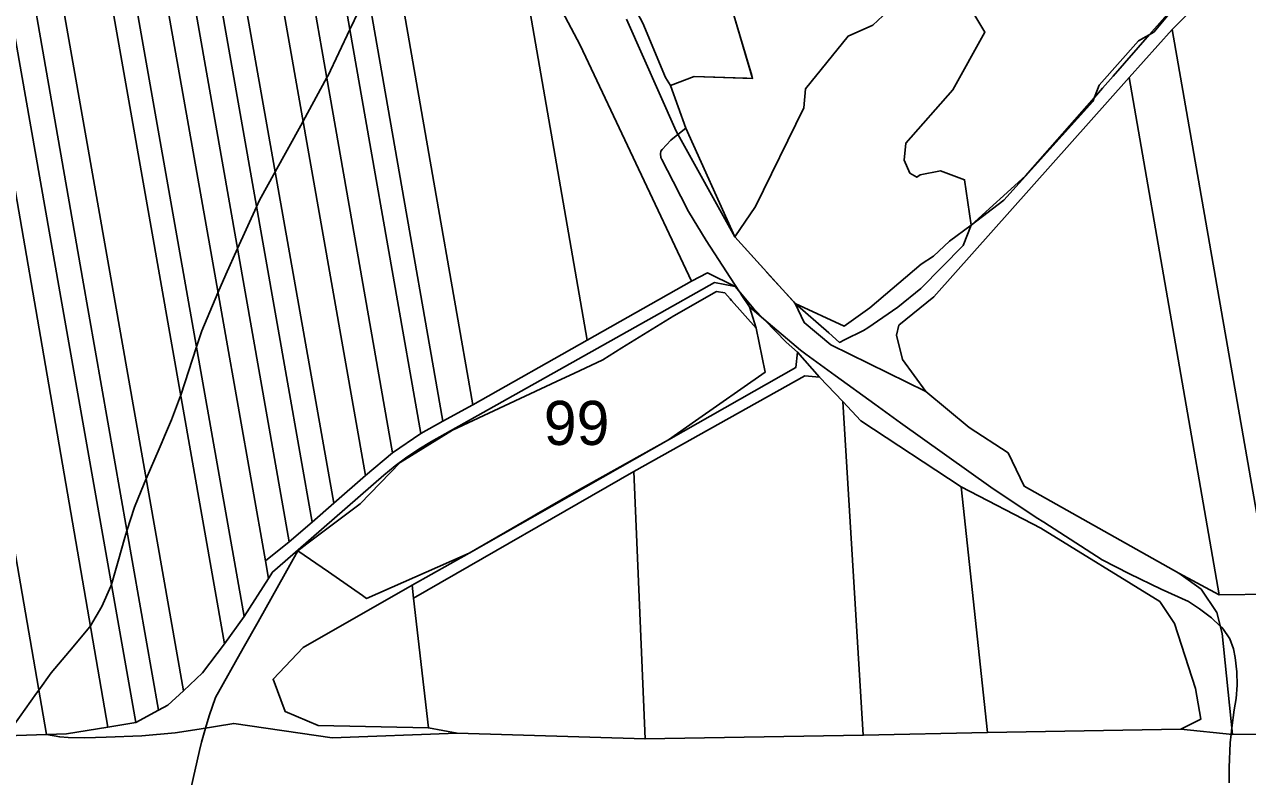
# Model space of a CAD drawing. Extents: x -521939 to -516426, y -1197857 to -1189551.
# Drawn here: x -518926.4 to -518510, y -1193004.4 to -1192748.4 of the extents above; entities that cross this region are included whole.
import ezdxf

# ---------------------------------------------------------------- set-up
doc = ezdxf.new("R2010")
doc.units = 0
for name, color, linetype in [('95560013', 7, 'Continuous'), ('95600013', 7, 'Continuous'), ('95610013', 7, 'Continuous'), ('95620013', 7, 'Continuous'), ('95640013', 7, 'Continuous'), ('95660013', 7, 'Continuous')]:
    doc.layers.add(name, color=color, linetype=linetype)

msp = doc.modelspace()

# ---------------------------------------------------------------- linework, layer by layer
at = {"layer": '95560013'}
for points in [[(-518883.96, -1192813.68), (-518944.06, -1192473.16), (-518936.14, -1192471.19), (-518905.14, -1192646.71), (-518874.14, -1192822.23), (-518851.6, -1192949.85), (-518858.28, -1192959.18)], [(-518924.38, -1192478.48), (-518893.68, -1192652.1), (-518862.98, -1192825.72), (-518844.38, -1192930.91), (-518843.32, -1192936.91), (-518851.6, -1192949.85), (-518874.14, -1192822.23), (-518905.14, -1192646.71), (-518936.14, -1192471.19), (-518930.23, -1192469.72)], [(-518960.05, -1192477.14), (-518952.49, -1192475.3), (-518944.06, -1192473.16), (-518883.96, -1192813.68), (-518858.28, -1192959.18), (-518865.75, -1192969.09), (-518872.22, -1192975.24), (-518898.04, -1192828.81)], [(-518969.05, -1192479.46), (-518937.77, -1192657.48), (-518906.62, -1192834.76), (-518880.78, -1192981.82), (-518888.53, -1192985.94), (-518914.36, -1192839.45), (-518945.91, -1192660.52), (-518977.46, -1192481.59)], [(-518872.22, -1192975.24), (-518877.56, -1192980.06), (-518880.78, -1192981.82), (-518906.62, -1192834.76), (-518937.77, -1192657.48), (-518969.05, -1192479.46), (-518960.05, -1192477.14), (-518898.04, -1192828.81)], [(-518911.42, -1192497.6), (-518879.74, -1192677.45), (-518848.71, -1192853.61), (-518836.23, -1192924.46), (-518844.38, -1192930.91), (-518862.98, -1192825.72), (-518893.68, -1192652.1), (-518924.38, -1192478.48)], [(-518897.98, -1192987.5), (-518912.11, -1192989.78), (-518918.87, -1192990), (-518944.92, -1192840.14), (-518975.46, -1192664.45), (-519006, -1192488.76), (-518985.24, -1192483.53), (-518954.55, -1192660.79), (-518920.43, -1192857.84)], [(-518945.91, -1192660.52), (-518914.36, -1192839.45), (-518888.53, -1192985.94), (-518897.98, -1192987.5), (-518920.43, -1192857.84), (-518954.55, -1192660.79), (-518985.24, -1192483.53), (-518977.46, -1192481.59)], [(-518932.53, -1192990.45), (-518956.69, -1192853.01), (-518988.4, -1192672.62), (-519020.11, -1192492.23), (-519006, -1192488.76), (-518975.46, -1192664.45), (-518944.92, -1192840.14), (-518918.87, -1192990)], [(-518911.42, -1192497.6), (-518899.32, -1192515.59), (-518868.08, -1192692.89), (-518836.84, -1192870.19), (-518828.46, -1192917.75), (-518836.23, -1192924.46), (-518848.71, -1192853.61), (-518879.74, -1192677.45)], [(-518888.04, -1192532.35), (-518856.66, -1192710.07), (-518825.31, -1192887.62), (-518821.12, -1192911.35), (-518828.46, -1192917.75), (-518836.84, -1192870.19), (-518868.08, -1192692.89), (-518899.32, -1192515.59)], [(-518888.04, -1192532.35), (-518871, -1192557.6), (-518840.17, -1192732.41), (-518810.28, -1192901.89), (-518821.12, -1192911.35), (-518825.31, -1192887.62), (-518856.66, -1192710.07)], [(-518871, -1192557.6), (-518856.13, -1192579.88), (-518825.13, -1192756.87), (-518801.08, -1192894.18), (-518810.28, -1192901.89), (-518840.17, -1192732.41)], [(-518810.26, -1192780.53), (-518791.49, -1192887.61), (-518801.08, -1192894.18), (-518825.13, -1192756.87), (-518856.13, -1192579.88), (-518842.04, -1192599.23)], [(-518842.04, -1192599.23), (-518831.07, -1192614.22), (-518800.38, -1192789.53), (-518783.94, -1192883.44), (-518791.49, -1192887.61), (-518810.26, -1192780.53)], [(-518786.19, -1192806.65), (-518773.74, -1192877.8), (-518783.94, -1192883.44), (-518800.38, -1192789.53), (-518831.07, -1192614.22), (-518816.35, -1192634.29)], [(-518759.71, -1192712.86), (-518734.84, -1192855.82), (-518773.74, -1192877.8), (-518786.19, -1192806.65), (-518816.35, -1192634.29)], [(-518699.31, -1192835.73), (-518734.84, -1192855.82), (-518759.71, -1192712.86), (-518737.24, -1192755.42)]]:
    msp.add_lwpolyline(points, close=True, dxfattribs=at)
at = {"layer": '95600013'}
msp.add_lwpolyline([(-518678.47, -1192766.77), (-518698.41, -1192766.11), (-518706.48, -1192769.16), (-518708.17, -1192766.43), (-518715.91, -1192747.94), (-518717.63, -1192744.59), (-518698.25, -1192731.89), (-518697.23, -1192734.65), (-518695.01, -1192738.2), (-518684.92, -1192745.27)], close=True, dxfattribs=at)
at = {"layer": '95610013'}
for points in [[(-518508.45, -1192727.51), (-518477.72, -1192903.66), (-518469.02, -1192953.53), (-518485.76, -1192945.93), (-518494.49, -1192943.25), (-518502, -1192942.29), (-518535.64, -1192750.15), (-518525.8, -1192740.06), (-518518.9, -1192734.37)], [(-518502, -1192942.29), (-518519.63, -1192942.55), (-518550.24, -1192766.43), (-518535.64, -1192750.15)], [(-518629.44, -1192854.17), (-518628.75, -1192850.78), (-518616.82, -1192841.07), (-518550.24, -1192766.43), (-518519.63, -1192942.55), (-518533.4, -1192935.15), (-518586.01, -1192905.56), (-518591.47, -1192894.23), (-518604.74, -1192885.62), (-518619.45, -1192873.36), (-518627.5, -1192862.37)], [(-518718.9, -1192900.54), (-518660.71, -1192868.02), (-518655.74, -1192868.43), (-518647.77, -1192876.73), (-518640.83, -1192990.3), (-518715.07, -1192991.54)], [(-518640.83, -1192990.3), (-518647.77, -1192876.73), (-518641.65, -1192883.29), (-518607.43, -1192905.72), (-518598.55, -1192989.35)], [(-518793.93, -1192943.67), (-518718.9, -1192900.54), (-518715.07, -1192991.54), (-518779.05, -1192989.61), (-518788.86, -1192987.81)], [(-518525.88, -1192984.87), (-518532.67, -1192988.21), (-518598.55, -1192989.35), (-518607.43, -1192905.72), (-518580.39, -1192919.85), (-518539.85, -1192944.8), (-518534.83, -1192952.24), (-518527.68, -1192974.39)], [(-518441.46, -1192991.31), (-518473.62, -1192989.89), (-518515.05, -1192990), (-518518.64, -1192955.67), (-518520.44, -1192948.52), (-518525.77, -1192940.63), (-518533.4, -1192935.15), (-518519.63, -1192942.55), (-518502, -1192942.29), (-518494.49, -1192943.25), (-518485.76, -1192945.93), (-518469.02, -1192953.53), (-518442.41, -1192965.03), (-518428.88, -1192969.95), (-518413.6, -1192975.54), (-518404.12, -1192979.78), (-518382.7, -1192989.47), (-518370.63, -1193001.75), (-518365.62, -1193004.33), (-518354.48, -1193010.65), (-518375.31, -1193003.18), (-518388.43, -1193000.81), (-518414.09, -1192994.92)], [(-518793.93, -1192943.67), (-518788.86, -1192987.81), (-518826.37, -1192986.96), (-518837.66, -1192982.24), (-518841.74, -1192971.22), (-518831.52, -1192960.42), (-518794.45, -1192939.2)]]:
    msp.add_lwpolyline(points, close=True, dxfattribs=at)
at = {"layer": '95620013'}
for points in [[(-518630.7, -1192742.29), (-518637.58, -1192748.61), (-518645.97, -1192752.33), (-518660.51, -1192770.33), (-518660.99, -1192776.79), (-518677.53, -1192810.38), (-518684.56, -1192820.7), (-518704.53, -1192784.74), (-518721.46, -1192746.65)], [(-518535.48, -1192743.39), (-518541.9, -1192751.07), (-518547.09, -1192753.93), (-518560.44, -1192769.05), (-518562.68, -1192774.61), (-518592.99, -1192808.25), (-518604.02, -1192816.75), (-518606.32, -1192801.23), (-518614.52, -1192798.26), (-518621.42, -1192799.62), (-518622.62, -1192800.39), (-518624.93, -1192798.97), (-518626.89, -1192794.58), (-518626.29, -1192788.78), (-518610.31, -1192770.59), (-518599.39, -1192750.98), (-518602.87, -1192745.31)], [(-518715.91, -1192747.94), (-518708.17, -1192766.43), (-518706.48, -1192769.16), (-518698.41, -1192766.11), (-518678.47, -1192766.77), (-518684.92, -1192745.27)]]:
    msp.add_lwpolyline(points, dxfattribs=at)
msp.add_lwpolyline([(-518821.67, -1192991.23), (-518855.17, -1192986.26), (-518866.91, -1192988.22), (-518875.1, -1192989.54), (-518886.48, -1192990.45), (-518898.64, -1192990.98), (-518905.82, -1192991.22), (-518911.52, -1192991.08), (-518914.36, -1192990.89), (-518918.87, -1192990), (-518912.11, -1192989.78), (-518897.98, -1192987.5), (-518888.53, -1192985.94), (-518880.78, -1192981.82), (-518877.56, -1192980.06), (-518872.22, -1192975.24), (-518865.75, -1192969.09), (-518858.28, -1192959.18), (-518851.6, -1192949.85), (-518843.32, -1192936.91), (-518841.93, -1192934.75), (-518837.69, -1192931.06), (-518804.08, -1192901.83), (-518800.23, -1192898.65), (-518796.23, -1192895.68), (-518792.08, -1192892.91), (-518787.8, -1192890.35), (-518712.04, -1192847.75), (-518691.51, -1192836.21), (-518684.41, -1192837.53), (-518678.07, -1192845.16), (-518667.06, -1192856.49), (-518663.19, -1192859.9), (-518663.78, -1192865.16), (-518707.15, -1192889.79), (-518774.96, -1192928.3), (-518794.45, -1192939.2), (-518831.52, -1192960.42), (-518841.74, -1192971.22), (-518837.66, -1192982.24), (-518826.37, -1192986.96), (-518788.86, -1192987.81), (-518779.05, -1192989.61)], close=True, dxfattribs=at)
at = {"layer": '95640013'}
for points in [[(-518721.46, -1192746.65), (-518704.53, -1192784.74), (-518684.56, -1192820.7), (-518663.98, -1192843.4), (-518660.97, -1192849.86), (-518651.89, -1192857.45), (-518619.45, -1192873.36), (-518604.74, -1192885.62), (-518591.47, -1192894.23), (-518586.01, -1192905.56), (-518533.4, -1192935.15), (-518525.77, -1192940.63), (-518520.44, -1192948.52), (-518518.64, -1192955.67), (-518515.05, -1192990), (-518532.67, -1192988.21), (-518525.88, -1192984.87), (-518527.68, -1192974.39), (-518534.83, -1192952.24), (-518539.85, -1192944.8), (-518580.39, -1192919.85), (-518607.43, -1192905.72), (-518641.65, -1192883.29), (-518647.77, -1192876.73), (-518655.74, -1192868.43), (-518663.19, -1192859.9), (-518667.06, -1192856.49), (-518678.07, -1192845.16), (-518684.41, -1192837.53), (-518693.82, -1192832.93), (-518699.31, -1192835.73), (-518737.24, -1192755.42), (-518759.71, -1192712.86)], [(-518602.87, -1192745.31), (-518599.39, -1192750.98), (-518610.31, -1192770.59), (-518626.29, -1192788.78), (-518626.89, -1192794.58), (-518624.93, -1192798.97), (-518622.62, -1192800.39), (-518621.42, -1192799.62), (-518614.52, -1192798.26), (-518606.32, -1192801.23), (-518604.02, -1192816.75), (-518611.45, -1192822.14), (-518616.94, -1192827.29), (-518621.09, -1192829.97), (-518638.52, -1192844.83), (-518647.3, -1192851.1), (-518663.98, -1192843.4), (-518684.56, -1192820.7), (-518677.53, -1192810.38), (-518660.99, -1192776.79), (-518660.51, -1192770.33), (-518645.97, -1192752.33), (-518637.58, -1192748.61), (-518630.7, -1192742.29)], [(-518525.8, -1192740.06), (-518535.64, -1192750.15), (-518550.24, -1192766.43), (-518616.82, -1192841.07), (-518628.75, -1192850.78), (-518629.44, -1192854.17), (-518627.5, -1192862.37), (-518619.45, -1192873.36), (-518651.89, -1192857.45), (-518660.97, -1192849.86), (-518663.98, -1192843.4), (-518647.3, -1192851.1), (-518638.52, -1192844.83), (-518621.09, -1192829.97), (-518616.94, -1192827.29), (-518611.45, -1192822.14), (-518604.02, -1192816.75), (-518592.99, -1192808.25), (-518562.68, -1192774.61), (-518560.44, -1192769.05), (-518547.09, -1192753.93), (-518541.9, -1192751.07), (-518535.48, -1192743.39)], [(-518932.53, -1192990.45), (-518918.87, -1192990), (-518914.36, -1192990.89), (-518911.52, -1192991.08), (-518905.82, -1192991.22), (-518898.64, -1192990.98), (-518886.48, -1192990.45), (-518875.1, -1192989.54), (-518866.91, -1192988.22), (-518855.17, -1192986.26), (-518821.67, -1192991.23), (-518779.05, -1192989.61), (-518715.07, -1192991.54), (-518640.83, -1192990.3), (-518598.55, -1192989.35), (-518532.67, -1192988.21), (-518515.05, -1192990), (-518473.62, -1192989.89)]]:
    msp.add_lwpolyline(points, dxfattribs=at)
for points in [[(-518734.84, -1192855.82), (-518699.31, -1192835.73), (-518693.82, -1192832.93), (-518684.41, -1192837.53), (-518691.51, -1192836.21), (-518712.04, -1192847.75), (-518787.8, -1192890.35), (-518792.08, -1192892.91), (-518796.23, -1192895.68), (-518800.23, -1192898.65), (-518804.08, -1192901.83), (-518837.69, -1192931.06), (-518841.93, -1192934.75), (-518843.32, -1192936.91), (-518844.38, -1192930.91), (-518836.23, -1192924.46), (-518828.46, -1192917.75), (-518821.12, -1192911.35), (-518810.28, -1192901.89), (-518801.08, -1192894.18), (-518791.49, -1192887.61), (-518783.94, -1192883.44), (-518773.74, -1192877.8)], [(-518655.74, -1192868.43), (-518660.71, -1192868.02), (-518718.9, -1192900.54), (-518793.93, -1192943.67), (-518794.45, -1192939.2), (-518774.96, -1192928.3), (-518707.15, -1192889.79), (-518663.78, -1192865.16), (-518663.19, -1192859.9)]]:
    msp.add_lwpolyline(points, close=True, dxfattribs=at)
at = {"layer": '95660013'}
for points in [[(-518930.03, -1192986.91), (-518922.26, -1192976.01), (-518921.49, -1192974.93), (-518917.28, -1192969.06), (-518911.02, -1192961.64), (-518904.18, -1192953.41), (-518903.95, -1192953.03), (-518900.01, -1192946.46), (-518897, -1192939.62), (-518896.81, -1192938.98), (-518894.45, -1192931.04), (-518892.24, -1192923.04), (-518891.5, -1192920.78), (-518888.88, -1192912.72), (-518885.64, -1192904.61), (-518884.95, -1192903.02), (-518880.54, -1192892.79), (-518879.56, -1192890.48), (-518878.73, -1192888.53), (-518876.36, -1192882.94), (-518873.58, -1192875.75), (-518873.21, -1192874.61), (-518867.81, -1192858.07), (-518866.05, -1192852.68), (-518860.51, -1192839.72), (-518857.82, -1192833.44), (-518853.82, -1192824.62), (-518847.37, -1192810.43), (-518846.34, -1192808.17), (-518841.03, -1192798.57), (-518832.32, -1192782.79), (-518831.54, -1192781.36), (-518823.44, -1192766.5), (-518823.16, -1192765.98), (-518815.6, -1192750.07), (-518809.53, -1192737.29)], [(-518809.53, -1192737.29), (-518815.6, -1192750.07), (-518823.16, -1192765.98), (-518823.44, -1192766.5), (-518831.54, -1192781.36), (-518832.32, -1192782.79), (-518841.03, -1192798.57), (-518846.34, -1192808.17), (-518847.37, -1192810.43), (-518853.82, -1192824.62), (-518857.82, -1192833.44), (-518860.51, -1192839.72), (-518866.05, -1192852.68), (-518867.81, -1192858.07), (-518873.21, -1192874.61), (-518873.58, -1192875.75), (-518876.36, -1192882.94), (-518878.73, -1192888.53), (-518879.56, -1192890.48), (-518880.54, -1192892.79), (-518884.95, -1192903.02), (-518885.64, -1192904.61), (-518888.88, -1192912.72), (-518891.5, -1192920.78), (-518892.24, -1192923.04), (-518894.45, -1192931.04), (-518896.81, -1192938.98), (-518897, -1192939.62), (-518900.01, -1192946.46), (-518903.95, -1192953.03), (-518904.18, -1192953.41), (-518911.02, -1192961.64), (-518917.28, -1192969.06), (-518921.49, -1192974.93), (-518922.26, -1192976.01), (-518930.03, -1192986.91)], [(-518516.26, -1193006.51), (-518516.26, -1193003.71), (-518516.18, -1193001.24), (-518515.91, -1192992.86), (-518515.55, -1192989.95), (-518515.28, -1192987.79), (-518514.51, -1192981.61), (-518513.81, -1192977.81), (-518513.46, -1192973.21), (-518513.58, -1192968.72), (-518514.16, -1192963.82), (-518514.74, -1192960.9), (-518516.02, -1192957.52), (-518518.36, -1192954.02), (-518519.28, -1192953.13), (-518522.21, -1192950.29), (-518526.29, -1192947.31), (-518530.02, -1192944.75), (-518539.35, -1192940.55), (-518550.14, -1192935.36), (-518559.41, -1192930.63), (-518579.36, -1192917.82), (-518581.93, -1192916.17), (-518597.38, -1192905.91), (-518628.12, -1192883.98), (-518636.83, -1192877.66), (-518650.39, -1192867.82), (-518660.35, -1192860.61), (-518662.17, -1192859.29), (-518674.68, -1192848.64), (-518679.55, -1192844.5), (-518682.12, -1192840.63), (-518682.62, -1192839.86), (-518683.15, -1192839.05), (-518694.31, -1192821.9), (-518700.26, -1192812.1), (-518705.51, -1192801.83), (-518709.36, -1192794.37), (-518709.68, -1192793.7), (-518709.88, -1192792.44), (-518709.71, -1192791.57), (-518709.33, -1192790.9), (-518706.32, -1192787.78), (-518703.91, -1192785.85), (-518701.16, -1192783.64), (-518684.56, -1192820.7), (-518673.64, -1192832.74), (-518673.59, -1192832.79), (-518664.5, -1192842.82), (-518663.98, -1192843.4), (-518652.55, -1192853.38), (-518648.85, -1192856.61), (-518647.17, -1192855.77), (-518640.72, -1192852.56), (-518639.28, -1192851.59), (-518629.03, -1192844.66), (-518621.2, -1192838.31), (-518606.75, -1192823.64), (-518604.02, -1192816.75), (-518585.53, -1192799.87), (-518562.11, -1192773.2), (-518559.38, -1192770.09), (-518555.73, -1192765.95), (-518543.3, -1192751.84), (-518534.68, -1192742.05)], [(-518534.68, -1192742.05), (-518543.3, -1192751.84), (-518555.73, -1192765.95), (-518559.38, -1192770.09), (-518562.11, -1192773.2), (-518585.53, -1192799.87), (-518604.02, -1192816.75), (-518606.75, -1192823.64), (-518621.2, -1192838.31), (-518629.03, -1192844.66), (-518639.28, -1192851.59), (-518640.72, -1192852.56), (-518647.17, -1192855.77), (-518648.85, -1192856.61), (-518652.55, -1192853.38), (-518663.98, -1192843.4), (-518664.5, -1192842.82), (-518673.59, -1192832.79), (-518673.64, -1192832.74), (-518684.56, -1192820.7), (-518701.16, -1192783.64), (-518706.48, -1192769.16), (-518698.41, -1192766.11), (-518680.89, -1192766.69), (-518680.5, -1192766.7), (-518678.47, -1192766.77), (-518678.76, -1192765.79), (-518684.92, -1192745.27)], [(-518684.92, -1192745.27), (-518678.76, -1192765.79), (-518678.47, -1192766.77), (-518680.5, -1192766.7), (-518680.89, -1192766.69), (-518698.41, -1192766.11), (-518706.48, -1192769.16), (-518701.16, -1192783.64), (-518703.91, -1192785.85), (-518706.32, -1192787.78), (-518709.33, -1192790.9), (-518709.71, -1192791.57), (-518709.88, -1192792.44), (-518709.68, -1192793.7), (-518709.36, -1192794.37), (-518705.51, -1192801.83), (-518700.26, -1192812.1), (-518694.31, -1192821.9), (-518683.15, -1192839.05), (-518682.62, -1192839.86), (-518682.12, -1192840.63), (-518679.55, -1192844.5), (-518677.32, -1192851.77), (-518685.71, -1192842.31), (-518686.16, -1192841.8), (-518687.95, -1192839.78), (-518690.83, -1192839.31), (-518705.27, -1192847.51), (-518723.04, -1192858.5), (-518729.53, -1192862.51), (-518739.3, -1192867.18), (-518743.53, -1192869.15), (-518780.7, -1192886.43), (-518798.47, -1192897.48), (-518812.08, -1192911.53), (-518830.21, -1192925.21), (-518833.3, -1192927.54), (-518846.85, -1192951.68), (-518851.92, -1192960.7), (-518861.34, -1192977.48), (-518863.51, -1192983.71), (-518864.73, -1192987.86), (-518866.15, -1192992.68), (-518866.79, -1192995.54), (-518869.73, -1193008.59)], [(-518869.73, -1193008.59), (-518866.79, -1192995.54), (-518866.15, -1192992.68), (-518864.73, -1192987.86), (-518863.51, -1192983.71), (-518861.34, -1192977.48), (-518851.92, -1192960.7), (-518846.85, -1192951.68), (-518833.3, -1192927.54), (-518822.89, -1192934.73), (-518811.28, -1192942.75), (-518809.89, -1192943.71), (-518797.36, -1192938.18), (-518785.78, -1192933.07), (-518774.96, -1192928.3), (-518753.25, -1192915.75), (-518752.6, -1192915.37), (-518752.04, -1192915.04), (-518739.27, -1192907.66), (-518707.15, -1192889.79), (-518697.92, -1192883.32), (-518674.26, -1192866.75), (-518677.32, -1192851.77), (-518679.55, -1192844.5), (-518674.68, -1192848.64), (-518662.17, -1192859.29), (-518660.35, -1192860.61), (-518650.39, -1192867.82), (-518636.83, -1192877.66), (-518628.12, -1192883.98), (-518597.38, -1192905.91), (-518581.93, -1192916.17), (-518579.36, -1192917.82), (-518559.41, -1192930.63), (-518550.14, -1192935.36), (-518539.35, -1192940.55), (-518530.02, -1192944.75), (-518526.29, -1192947.31), (-518522.21, -1192950.29), (-518519.28, -1192953.13), (-518518.36, -1192954.02), (-518516.02, -1192957.52), (-518514.74, -1192960.9), (-518514.16, -1192963.82), (-518513.58, -1192968.72), (-518513.46, -1192973.21), (-518513.81, -1192977.81), (-518514.51, -1192981.61), (-518515.28, -1192987.79), (-518515.55, -1192989.95), (-518515.91, -1192992.86), (-518516.18, -1193001.24), (-518516.26, -1193003.71), (-518516.26, -1193006.51)]]:
    msp.add_lwpolyline(points, dxfattribs=at)
msp.add_lwpolyline([(-518797.36, -1192938.18), (-518809.89, -1192943.71), (-518811.28, -1192942.75), (-518822.89, -1192934.73), (-518833.3, -1192927.54), (-518830.21, -1192925.21), (-518812.08, -1192911.53), (-518798.47, -1192897.48), (-518780.7, -1192886.43), (-518743.53, -1192869.15), (-518739.3, -1192867.18), (-518729.53, -1192862.51), (-518723.04, -1192858.5), (-518705.27, -1192847.51), (-518690.83, -1192839.31), (-518687.95, -1192839.78), (-518686.16, -1192841.8), (-518685.71, -1192842.31), (-518677.32, -1192851.77), (-518674.26, -1192866.75), (-518697.92, -1192883.32), (-518707.15, -1192889.79), (-518739.27, -1192907.66), (-518752.04, -1192915.04), (-518752.6, -1192915.37), (-518753.25, -1192915.75), (-518774.96, -1192928.3), (-518785.78, -1192933.07)], close=True, dxfattribs=at)

# ---------------------------------------------------------------- texts
msp.add_text('99', height=15, rotation=360, dxfattribs=at).set_placement((-518749.56, -1192891.51))

doc.saveas('drawing.dxf')
